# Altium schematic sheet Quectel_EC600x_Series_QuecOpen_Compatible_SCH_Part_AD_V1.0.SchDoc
size A2
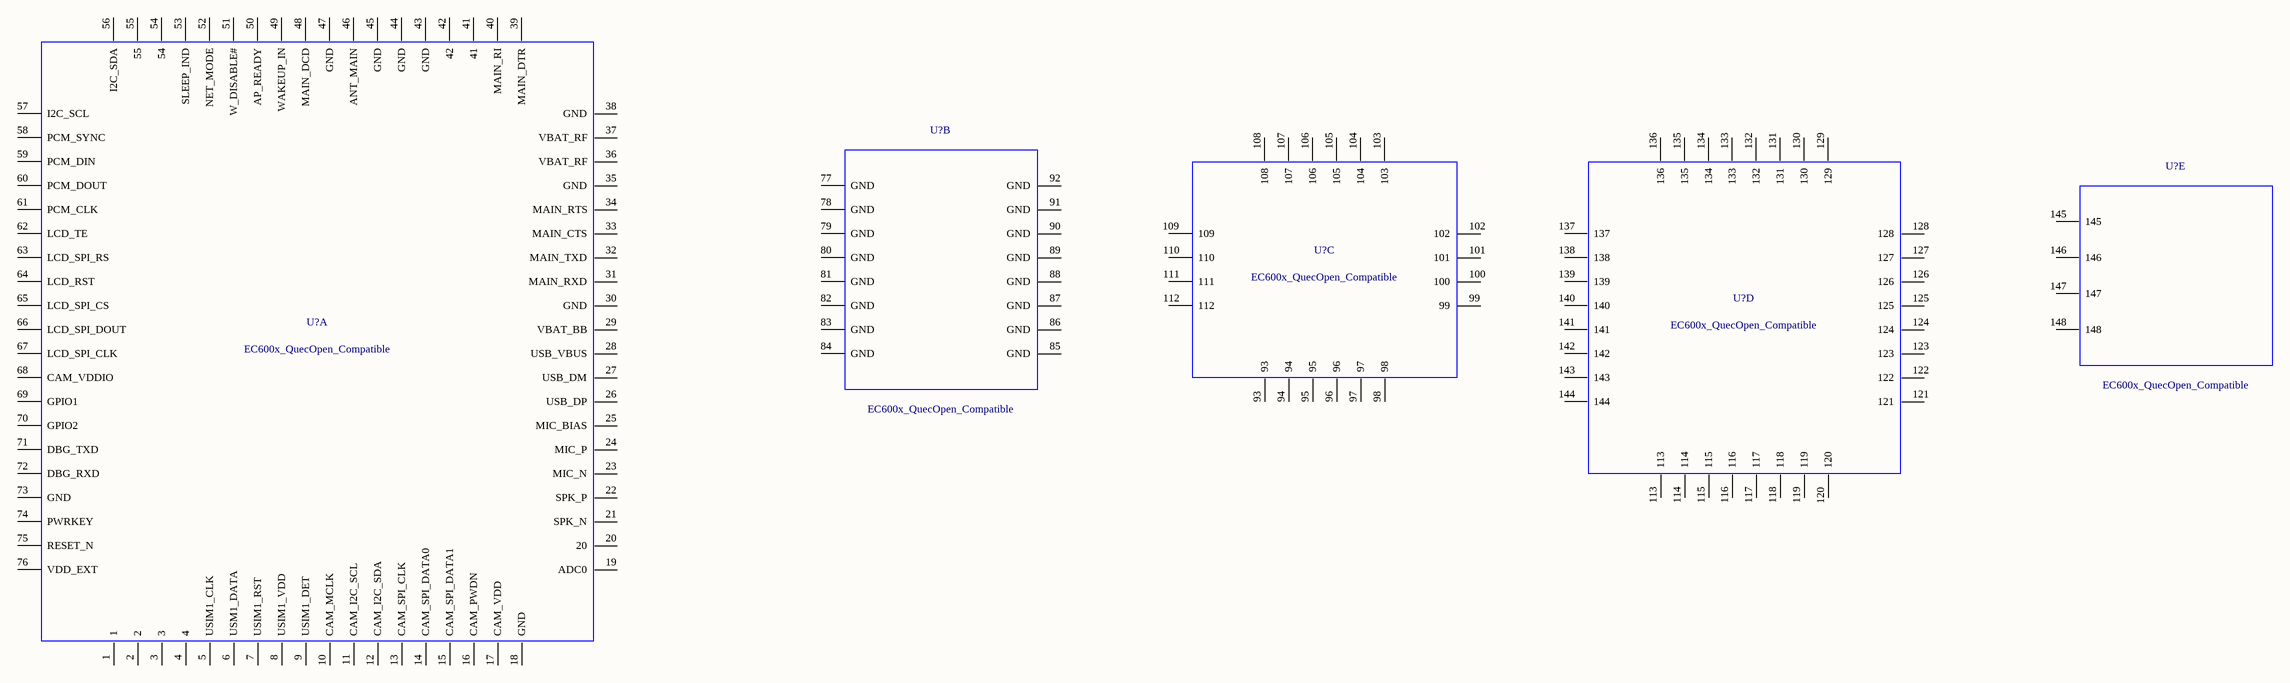
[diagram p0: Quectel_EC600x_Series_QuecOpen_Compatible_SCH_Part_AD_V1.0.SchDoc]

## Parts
(Parts that share a designator on the sheet are numbered #1, #2 ... from top to bottom, then left to right.)
U?#1  EC600x_QuecOpen_Compatible  (part B of 5)
U?#2  EC600x_QuecOpen_Compatible  (part C of 5)
U?#3  EC600x_QuecOpen_Compatible  (part E of 5)
U?#4  EC600x_QuecOpen_Compatible  (part D of 5)
U?#5  EC600x_QuecOpen_Compatible  (part A of 5)

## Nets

Not connected (* = marked no-connect by the designer): U?#1 77(GND) 78(GND) 79(GND) 80(GND) 81(GND) 82(GND) 83(GND) 84(GND) 85(GND) 86(GND) 87(GND) 88(GND) 89(GND) 90(GND) 91(GND) 92(GND); U?#2 93 94 95 96 97 98 99 100 101 102 103 104 105 106 107 108 109 110 111 112; U?#3 145 146 147 148; U?#4 113 114 115 116 117 118 119 120 121 122 123 124 125 126 127 128 129 130 131 132 133 134 135 136 137 138 139 140 141 142 143 144; U?#5 1 2 3 4 5(USIM1_CLK) 6(USM1_DATA) 7(USIM1_RST) 8(USIM1_VDD) 9(USIM1_DET) 10(CAM_MCLK) 11(CAM_I2C_SCL) 12(CAM_I2C_SDA) 13(CAM_SPI_CLK) 14(CAM_SPI_DATA0) 15(CAM_SPI_DATA1) 16(CAM_PWDN) 17(CAM_VDD) 18(GND) 19(ADC0) 20 21(SPK_N) 22(SPK_P) 23(MIC_N) 24(MIC_P) 25(MIC_BIAS) 26(USB_DP) 27(USB_DM) 28(USB_VBUS) 29(VBAT_BB) 30(GND) 31(MAIN_RXD) 32(MAIN_TXD) 33(MAIN_CTS) 34(MAIN_RTS) 35(GND) 36(VBAT_RF) 37(VBAT_RF) 38(GND) 39(MAIN_DTR) 40(MAIN_RI) 41 42 43(GND) 44(GND) 45(GND) 46(ANT_MAIN) 47(GND) 48(MAIN_DCD) 49(WAKEUP_IN) 50(AP_READY) 51(W_DISABLE#) 52(NET_MODE) 53(SLEEP_IND) 54 55 56(I2C_SDA) 57(I2C_SCL) 58(PCM_SYNC) 59(PCM_DIN) 60(PCM_DOUT) 61(PCM_CLK) 62(LCD_TE) 63(LCD_SPI_RS) 64(LCD_RST) 65(LCD_SPI_CS) 66(LCD_SPI_DOUT) 67(LCD_SPI_CLK) 68(CAM_VDDIO) 69(GPIO1) 70(GPIO2) 71(DBG_TXD) 72(DBG_RXD) 73(GND) 74(PWRKEY) 75(RESET_N) 76(VDD_EXT)

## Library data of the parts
U?#1-U?#4 = EC600X_QUECOPEN_COMPATIBLE: EC600x_QuecOpen_Compatible Module LCC76PIN LGA72PIN H2.4mm RO; Manufacturer: Quectel; Geometry.Height: 2.4mm
U?#5 = EC600x_QuecOpen_Compatible: EC600x_QuecOpen_Compatible Module LCC76PIN LGA72PIN H2.4mm RO; Manufacturer: Quectel; Geometry.Height: 2.4mm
